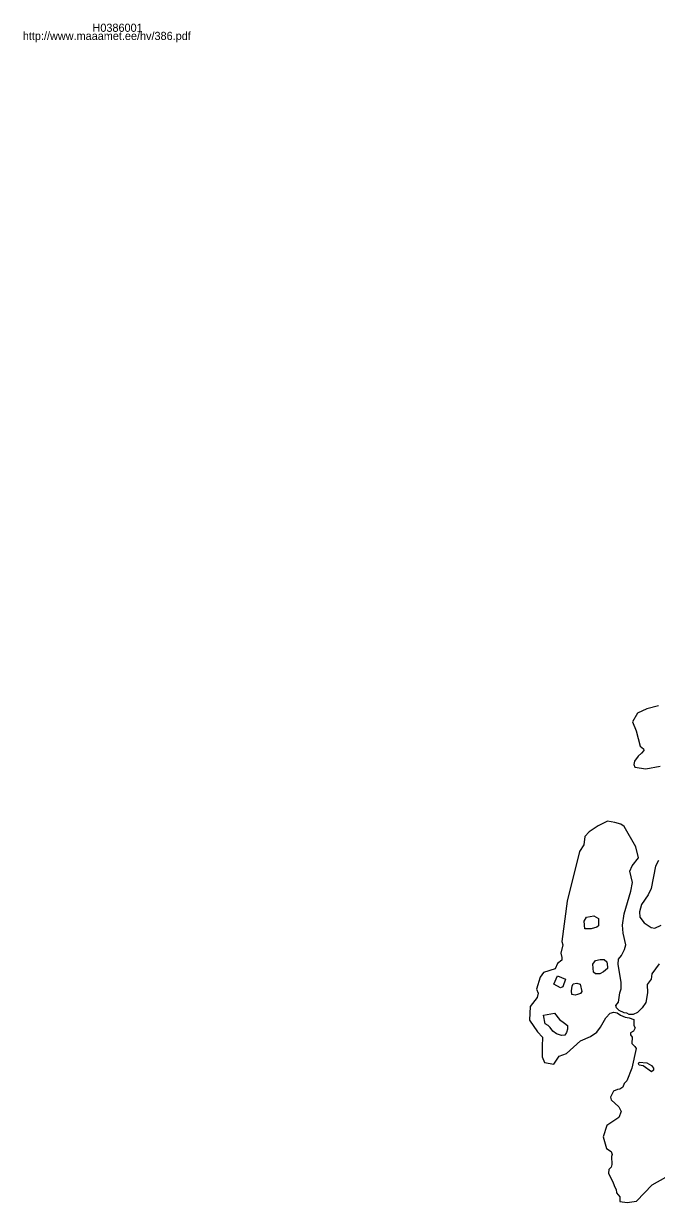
# Model space of a CAD drawing. Extents: x 369010 to 739155, y 6377141 to 6634081.
# Drawn here: x 443794 to 445740, y 6474326 to 6477950 of the extents above; entities that cross this region are included whole.
import ezdxf

# ---------------------------------------------------------------- set-up
doc = ezdxf.new("R2010")
doc.units = 0
for name, color, linetype in [('H_LINK', 7, 'Continuous'), ('H_PIIR', 7, 'Continuous'), ('H_TUNNUS', 7, 'Continuous')]:
    doc.layers.add(name, color=color, linetype=linetype)

msp = doc.modelspace()

# ---------------------------------------------------------------- linework, layer by layer
at = {"layer": 'H_PIIR'}
for points in [[(445746.6138, 6475853.1621), (445710.96, 6475843.92), (445681.74, 6475829.95), (445666.92, 6475803.27), (445677.9888, 6475776.1518), (445689.9538, 6475728.2522), (445700.9838, 6475720.9821), (445701.7939, 6475715.6022), (445694.6638, 6475706.7121), (445684.4337, 6475698.3622), (445672.8637, 6475682.4821), (445670.7039, 6475672.2522), (445673.6738, 6475664.4421), (445707.7334, 6475658.829), (445752.1835, 6475666.7666)], [(445748.9937, 6475059.0522), (445726.3138, 6475028.4222), (445723.9638, 6475012.2222), (445712.1839, 6474995.7321), (445713.3639, 6474970.7022), (445707.9138, 6474940.3621), (445696.4238, 6474924.1721), (445681.7039, 6474909.7421), (445668.4538, 6474904.1421), (445656.3838, 6474904.1421), (445649.3139, 6474907.6721), (445641.0638, 6474908.5622), (445625.7538, 6474915.9222), (445617.8038, 6474924.4621), (445616.0338, 6474931.2321), (445623.9839, 6474941.8422), (445627.5238, 6474970.1122), (445631.4939, 6474983.0721), (445631.4939, 6475002.5022), (445622.3638, 6475058.4622), (445623.6938, 6475073.7721), (445632.8238, 6475084.6721), (445642.5338, 6475103.2321), (445645.7737, 6475118.2521), (445638.4139, 6475153.5922), (445636.0639, 6475178.0322), (445641.5038, 6475213.3721), (445661.8238, 6475283.1721), (445666.9938, 6475309.0921), (445659.0437, 6475344.4421), (445666.1039, 6475360.3422), (445685.3938, 6475385.3721), (445677.1771, 6475418.7785), (445641.5874, 6475482.087), (445631.004, 6475488.7016), (445612.4832, 6475493.9933), (445589.9935, 6475497.9621), (445561.1338, 6475483.4421), (445533.2937, 6475465.4821), (445520.0439, 6475450.7522), (445517.1037, 6475425.4322), (445504.1438, 6475405.1021), (445465.6391, 6475251.8991), (445449.1139, 6475128.2522), (445452.6439, 6475117.6521), (445446.0238, 6475092.0322), (445449.8538, 6475078.7722), (445448.9637, 6475071.1222), (445436.3037, 6475060.5121), (445428.6438, 6475044.3221), (445393.0137, 6475032.8321), (445382.7137, 6475018.1022), (445371.9638, 6474981.5821), (445376.9739, 6474969.5122), (445373.4337, 6474956.5521), (445352.5338, 6474928.5722), (445349.7514, 6474886.7733), (445374.3577, 6474850.2608), (445390.2327, 6474833.592), (445388.6452, 6474805.0169), (445389.439, 6474774.0606), (445396.5827, 6474755.8043), (445424.5438, 6474750.9722), (445441.6239, 6474775.4221), (445463.7038, 6474783.9621), (445506.5438, 6474822.8421), (445537.7538, 6474836.0921), (445556.6038, 6474849.6422), (445568.3837, 6474864.3621), (445584.2838, 6474893.5222), (445598.2738, 6474907.9522), (445608.8737, 6474910.8922), (445620.0638, 6474909.1322), (445629.4938, 6474901.4722), (445644.5038, 6474895.2822), (445656.2839, 6474893.8121), (445671.0138, 6474887.9221), (445670.7139, 6474870.2522), (445675.4238, 6474862.3022), (445669.5339, 6474852.8721), (445660.9938, 6474847.5721), (445660.7037, 6474841.0921), (445665.5539, 6474834.3321), (445664.9739, 6474814.3022), (445674.3938, 6474805.4621), (445677.6339, 6474799.2822), (445664.6738, 6474738.3122), (445649.5138, 6474699.4421), (445640.9738, 6474692.0722), (445636.5637, 6474680.8821), (445627.7238, 6474674.4021), (445620.9537, 6474673.5222), (445608.5838, 6474667.6321), (445599.3038, 6474649.9622), (445600.7737, 6474641.7121), (445624.9238, 6474619.9222), (445632.2838, 6474605.7821), (445624.6238, 6474586.9321), (445587.8138, 6474562.4921), (445576.7738, 6474527.7322), (445587.0839, 6474491.5121), (445600.9239, 6474482.9721), (445604.7537, 6474473.5422), (445602.3938, 6474467.6522), (445603.7139, 6474442.9122), (445601.3637, 6474434.3721), (445594.0039, 6474427.3022), (445593.4139, 6474416.1121), (445607.5438, 6474386.6621), (445611.9638, 6474373.1122), (445616.9739, 6474366.0422), (445617.1138, 6474355.7422), (445627.4139, 6474342.7821), (445628.3038, 6474329.2322), (445650.7266, 6474326.065), (445679.3016, 6474330.0338), (445727.7174, 6474380.2365), (445769.7893, 6474403.8527)], [(445746.3638, 6475377.1121), (445737.9838, 6475360.0321), (445724.4338, 6475291.4021), (445715.0137, 6475271.6721), (445694.2437, 6475241.9322), (445688.0539, 6475218.9622), (445689.8238, 6475203.3522), (445702.7838, 6475185.3822), (445723.9838, 6475171.2421), (445735.7637, 6475168.8921), (445754.7742, 6475178.5542)]]:
    msp.add_lwpolyline(points, dxfattribs=at)
for points in [[(445518.5559, 6475191.0448), (445525.1705, 6475202.951), (445547.6601, 6475206.9198), (445562.2122, 6475198.9823), (445562.2122, 6475176.4927), (445556.9206, 6475172.5239), (445539.7226, 6475167.2322), (445519.8788, 6475167.2322)], [(445545.0143, 6475058.7528), (445552.9518, 6475069.3362), (445567.5039, 6475073.305), (445579.4102, 6475073.305), (445587.3477, 6475065.3674), (445589.9935, 6475050.8153), (445589.9935, 6475045.5236), (445578.0873, 6475034.9403), (445566.181, 6475028.3257), (445552.9518, 6475028.3257), (445546.3372, 6475033.6174)], [(445424.6286, 6474996.5756), (445436.5349, 6475023.034), (445460.3475, 6475012.4507), (445452.4099, 6474988.6381), (445445.7953, 6474985.9923)], [(445481.5142, 6474991.284), (445484.16, 6474997.8986), (445496.0663, 6475000.5444), (445505.3267, 6474996.5756), (445510.6184, 6474974.086), (445506.6496, 6474968.7943), (445497.3892, 6474964.8256), (445490.7746, 6474963.5027), (445480.1912, 6474964.8256), (445478.8683, 6474976.7318)], [(445392.8786, 6474901.3254), (445427.2745, 6474907.94), (445441.8266, 6474888.0963), (445457.7016, 6474877.5129), (445466.9621, 6474869.5754), (445466.9621, 6474858.992), (445464.3162, 6474848.4087), (445459.0245, 6474840.4712), (445448.4412, 6474839.1482), (445432.5661, 6474844.4399), (445421.9828, 6474852.3774), (445414.0453, 6474864.2837), (445407.4307, 6474869.5754), (445398.1702, 6474874.8671)], [(445725.0821, 6474728.0352), (445699.4291, 6474745.9096), (445687.3472, 6474748.3921), (445685.3612, 6474752.5298), (445687.3472, 6474757.1639), (445710.8488, 6474755.6744), (445725.413, 6474747.3991), (445731.2058, 6474739.124), (445731.5367, 6474732.3383)]]:
    msp.add_lwpolyline(points, close=True, dxfattribs=at)

# ---------------------------------------------------------------- texts
at = {"layer": 'H_LINK'}
msp.add_text('http://www.maaamet.ee/hv/386.pdf', height=25, rotation=360, dxfattribs=at).set_placement((443791.7745, 6477899.7193))
at = {"layer": 'H_TUNNUS'}
msp.add_text('H0386001', height=25, rotation=360, dxfattribs=at).set_placement((444006.1284, 6477924.7193))

doc.saveas('drawing.dxf')
